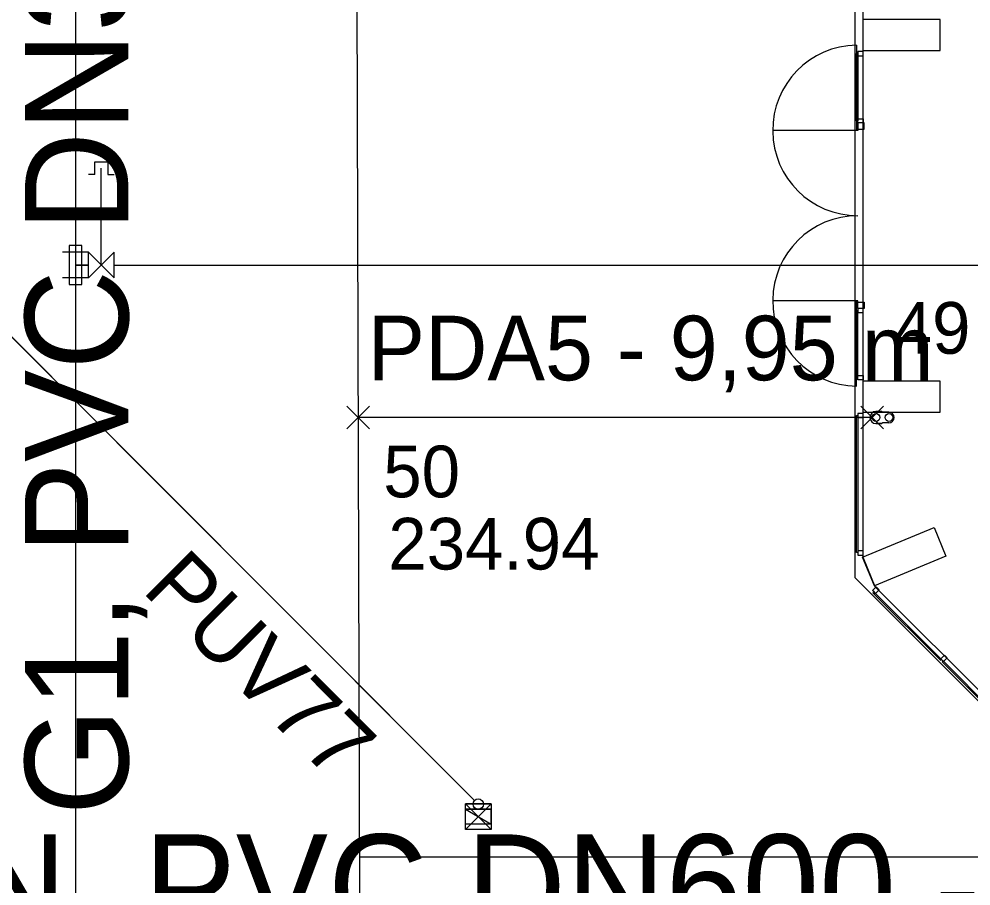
# Model space of a CAD drawing. Extents: x -264234 to -263604, y -1242346 to -1242049.
# Drawn here: x -263925.24 to -263906.8, y -1242233.35 to -1242216.57 of the extents above; entities that cross this region are included whole.
import ezdxf

# ---------------------------------------------------------------- set-up
doc = ezdxf.new("R2010")
doc.units = 0
for name, color, linetype in [('KFA_BODY_CISLO', 7, 'Continuous'), ('KFA_BODY_SYMBOL', 7, 'Continuous'), ('KFA_BODY_VYSKA', 7, 'Continuous'), ('KFA_DAZDOVA_KANALIZACIA_pripojky_tA_tC', 7, 'Continuous'), ('KFA_DAZDOVA_KANALIZACIA_pripojky_tA_tC_popis', 7, 'Continuous'), ('KFA_DAZDOVA_KANALIZACIA_retencna_nadrz_popis', 7, 'Continuous'), ('KFA_DAZDOVA_KANALIZACIA_vetva_G_popis', 7, 'Continuous'), ('KFA_JESTV_IS_DSP_-_KANAL_DAZD', 7, 'Continuous'), ('KFA_SITUACIA_DSP', 7, 'Continuous'), ('KFA_SO_40-2-II_DK_PRIPOJKY_UV_PROJEKT', 7, 'Continuous'), ('KFA_SO_40-2-II_DK_PRIPOJKY_UV_PROJEKT_popis', 7, 'Continuous'), ('KFA_SO_40-2-II_DK_UV_PROJEKT', 7, 'Continuous')]:
    doc.layers.add(name, color=color, linetype=linetype)

msp = doc.modelspace()

# ---------------------------------------------------------------- linework, layer by layer
at = {"layer": 'KFA_BODY_SYMBOL'}
for p, q in [((-263918.891, -1242224.504), (-263918.449, -1242224.062)), ((-263918.449, -1242224.504), (-263918.891, -1242224.062)), ((-263908.939, -1242224.503), (-263908.497, -1242224.061)), ((-263908.497, -1242224.503), (-263908.939, -1242224.061))]:
    msp.add_line(p, q, dxfattribs=at)
at = {"layer": 'KFA_DAZDOVA_KANALIZACIA_pripojky_tA_tC'}
msp.add_line((-263908.718, -1242224.282), (-263918.67, -1242224.283), dxfattribs=at)
at = {"layer": 'KFA_JESTV_IS_DSP_-_KANAL_DAZD'}
msp.add_line((-263918.755, -1242197.225), (-263918.632, -1242236.449), dxfattribs=at)
at = {"layer": 'KFA_SITUACIA_DSP'}
for p, q in [((-263924.143, -1242185.14), (-263924.143, -1242250.14)), ((-263908.893, -1242226.995), (-263908.893, -1242203.332)), ((-263907.398, -1242216.582), (-263908.898, -1242216.582)), ((-263908.898, -1242216.582), (-263908.898, -1242217.182)), ((-263907.398, -1242217.182), (-263907.398, -1242216.582)), ((-263909.018, -1242217.077), (-263909.018, -1242218.727)), ((-263909.018, -1242218.542), (-263909.018, -1242217.242)), ((-263909.018, -1242217.242), (-263908.993, -1242217.242)), ((-263908.893, -1242217.202), (-263908.993, -1242217.202)), ((-263908.993, -1242217.202), (-263908.993, -1242217.242)), ((-263908.993, -1242217.242), (-263908.993, -1242218.542)), ((-263908.993, -1242217.242), (-263908.993, -1242217.282)), ((-263908.898, -1242217.182), (-263907.398, -1242217.182)), ((-263908.893, -1242217.282), (-263908.893, -1242217.202)), ((-263908.993, -1242217.282), (-263908.893, -1242217.282)), ((-263908.993, -1242218.542), (-263909.018, -1242218.542)), ((-263908.993, -1242218.542), (-263908.993, -1242218.502)), ((-263908.993, -1242218.502), (-263908.893, -1242218.502)), ((-263908.993, -1242218.582), (-263908.993, -1242218.542)), ((-263908.893, -1242218.502), (-263908.893, -1242218.582)), ((-263908.993, -1242218.727), (-263910.643, -1242218.727)), ((-263908.893, -1242218.582), (-263908.993, -1242218.582)), ((-263908.873, -1242218.582), (-263908.993, -1242218.582)), ((-263908.993, -1242218.582), (-263908.993, -1242218.702)), ((-263908.993, -1242218.702), (-263908.993, -1242218.727)), ((-263908.993, -1242218.702), (-263908.873, -1242218.702)), ((-263908.873, -1242218.702), (-263908.873, -1242218.582)), ((-263923.768, -1242219.582), (-263923.768, -1242219.332)), ((-263923.768, -1242219.332), (-263923.518, -1242219.332)), ((-263923.643, -1242221.332), (-263923.643, -1242219.457)), ((-263923.518, -1242219.332), (-263923.518, -1242219.582)), ((-263923.768, -1242219.582), (-263923.893, -1242219.582)), ((-263923.518, -1242219.582), (-263923.393, -1242219.582)), ((-263923.893, -1242221.082), (-263924.393, -1242221.082)), ((-263924.018, -1242220.957), (-263924.268, -1242220.957)), ((-263924.268, -1242220.957), (-263924.268, -1242221.707)), ((-263924.018, -1242221.707), (-263924.018, -1242220.957)), ((-263923.893, -1242221.582), (-263923.893, -1242221.082)), ((-263923.893, -1242221.082), (-263923.393, -1242221.582)), ((-263923.393, -1242221.082), (-263923.893, -1242221.582)), ((-263923.393, -1242221.582), (-263923.393, -1242221.082)), ((-263924.143, -1242221.332), (-263923.893, -1242221.332)), ((-263923.893, -1242221.332), (-263924.143, -1242221.332)), ((-263923.393, -1242221.332), (-263903.343, -1242221.332)), ((-263923.893, -1242221.582), (-263924.393, -1242221.582)), ((-263924.268, -1242221.707), (-263924.018, -1242221.707)), ((-263916.414, -1242231.691), (-263926.24, -1242221.865)), ((-263908.993, -1242222.027), (-263910.643, -1242222.027)), ((-263909.018, -1242223.677), (-263909.018, -1242222.027)), ((-263908.993, -1242222.052), (-263908.993, -1242222.027)), ((-263909.018, -1242222.212), (-263909.018, -1242223.512)), ((-263908.993, -1242222.212), (-263909.018, -1242222.212)), ((-263908.993, -1242222.052), (-263908.873, -1242222.052)), ((-263908.993, -1242222.172), (-263908.993, -1242222.052)), ((-263908.893, -1242222.172), (-263908.993, -1242222.172)), ((-263908.993, -1242222.172), (-263908.993, -1242222.212)), ((-263908.873, -1242222.172), (-263908.993, -1242222.172)), ((-263908.993, -1242223.512), (-263908.993, -1242222.212)), ((-263908.993, -1242222.212), (-263908.993, -1242222.252)), ((-263908.893, -1242222.252), (-263908.893, -1242222.172)), ((-263908.873, -1242222.052), (-263908.873, -1242222.172)), ((-263908.993, -1242222.252), (-263908.893, -1242222.252)), ((-263909.018, -1242223.512), (-263908.993, -1242223.512)), ((-263908.993, -1242223.512), (-263908.993, -1242223.472)), ((-263908.993, -1242223.472), (-263908.893, -1242223.472)), ((-263908.993, -1242223.552), (-263908.993, -1242223.512)), ((-263908.893, -1242223.472), (-263908.893, -1242223.552)), ((-263908.893, -1242223.552), (-263908.993, -1242223.552)), ((-263907.398, -1242223.582), (-263908.898, -1242223.582)), ((-263908.898, -1242223.582), (-263908.898, -1242224.182)), ((-263907.398, -1242224.182), (-263907.398, -1242223.582)), ((-263909.018, -1242226.892), (-263909.018, -1242224.242)), ((-263909.018, -1242224.242), (-263908.993, -1242224.242)), ((-263908.893, -1242224.202), (-263908.993, -1242224.202)), ((-263908.993, -1242224.202), (-263908.993, -1242224.242)), ((-263908.993, -1242224.242), (-263908.993, -1242226.892)), ((-263908.993, -1242224.242), (-263908.993, -1242224.282)), ((-263908.898, -1242224.182), (-263907.398, -1242224.182)), ((-263908.893, -1242224.282), (-263908.893, -1242224.202)), ((-263908.532, -1242224.165), (-263908.643, -1242224.165)), ((-263908.518, -1242224.179), (-263908.532, -1242224.165)), ((-263908.393, -1242224.179), (-263908.518, -1242224.179)), ((-263908.718, -1242224.282), (-263918.67, -1242224.282)), ((-263908.993, -1242224.282), (-263908.893, -1242224.282)), ((-263908.643, -1242224.399), (-263908.532, -1242224.399)), ((-263908.532, -1242224.399), (-263908.643, -1242224.399)), ((-263908.518, -1242224.385), (-263908.532, -1242224.399)), ((-263908.393, -1242224.385), (-263908.518, -1242224.385)), ((-263908.903, -1242226.985), (-263907.518, -1242226.411)), ((-263907.518, -1242226.411), (-263907.288, -1242226.966)), ((-263908.993, -1242226.892), (-263909.018, -1242226.892)), ((-263908.893, -1242226.865), (-263908.993, -1242226.865)), ((-263908.993, -1242226.865), (-263908.993, -1242226.905)), ((-263908.993, -1242226.905), (-263908.993, -1242226.945)), ((-263908.993, -1242226.945), (-263908.893, -1242226.945)), ((-263908.674, -1242227.54), (-263908.903, -1242226.985)), ((-263908.893, -1242226.945), (-263908.893, -1242226.865)), ((-263908.893, -1242226.995), (-263908.663, -1242227.55)), ((-263907.288, -1242226.966), (-263908.674, -1242227.54)), ((-263908.709, -1242227.631), (-263908.638, -1242227.56)), ((-263908.663, -1242227.55), (-263895.135, -1242241.078)), ((-263908.638, -1242227.56), (-263908.581, -1242227.617)), ((-263908.68, -1242227.659), (-263908.709, -1242227.631)), ((-263908.685, -1242227.654), (-263908.703, -1242227.672)), ((-263908.703, -1242227.672), (-263907.395, -1242228.98)), ((-263907.377, -1242228.963), (-263908.685, -1242227.654)), ((-263908.652, -1242227.688), (-263908.68, -1242227.659)), ((-263908.581, -1242227.617), (-263908.652, -1242227.688)), ((-263907.395, -1242228.98), (-263907.377, -1242228.963)), ((-263907.39, -1242228.95), (-263907.319, -1242228.879)), ((-263907.361, -1242228.978), (-263907.39, -1242228.95)), ((-263907.363, -1242229.012), (-263907.345, -1242228.994)), ((-263906.055, -1242230.32), (-263907.363, -1242229.012)), ((-263907.333, -1242229.007), (-263907.361, -1242228.978)), ((-263907.345, -1242228.994), (-263906.037, -1242230.303)), ((-263907.262, -1242228.936), (-263907.333, -1242229.007)), ((-263907.319, -1242228.879), (-263907.262, -1242228.936)), ((-263916.593, -1242231.862), (-263916.093, -1242231.862)), ((-263916.593, -1242232.152), (-263916.593, -1242231.862)), ((-263916.593, -1242231.862), (-263916.093, -1242232.152)), ((-263916.593, -1242231.862), (-263916.093, -1242232.152)), ((-263916.093, -1242231.862), (-263916.593, -1242231.862)), ((-263916.093, -1242231.862), (-263916.093, -1242232.152)), ((-263916.093, -1242232.152), (-263916.093, -1242231.862)), ((-263916.093, -1242232.152), (-263916.593, -1242232.152)), ((-263905.894, -1242232.793), (-263918.643, -1242232.793))]:
    msp.add_line(p, q, dxfattribs=at)
msp.add_lwpolyline([(-263794.893, -1242227.382), (-263808.968, -1242241.457), (-263894.968, -1242241.457), (-263909.043, -1242227.382), (-263909.043, -1242196.333), (-263914.143, -1242196.333), (-263914.143, -1242132.433), (-263909.043, -1242132.433), (-263909.043, -1242101.382), (-263894.968, -1242087.307), (-263808.968, -1242087.307), (-263794.893, -1242101.382), (-263794.893, -1242227.382)], dxfattribs=at)
for centre, radius in [((-263908.643, -1242224.282), 0.075), ((-263908.393, -1242224.282), 0.075), ((-263916.343, -1242231.762), 0.1)]:
    msp.add_circle(centre, radius, dxfattribs=at)
for centre, radius, start, end in [((-263908.993, -1242218.727), 1.65, 90.8682, 270), ((-263908.993, -1242222.027), 1.65, 90, 269.1318), ((-263908.643, -1242224.282), 0.117, 90, 270), ((-263908.393, -1242224.282), 0.103, 270, 90)]:
    msp.add_arc(centre, radius, start, end, dxfattribs=at)
at = {"layer": 'KFA_SO_40-2-II_DK_PRIPOJKY_UV_PROJEKT'}
msp.add_lwpolyline([(-263916.414, -1242231.691), (-263926.24, -1242221.865)], dxfattribs=at)
at = {"layer": 'KFA_SO_40-2-II_DK_UV_PROJEKT'}
msp.add_lwpolyline([(-263916.593, -1242232.257), (-263916.593, -1242231.757), (-263916.093, -1242231.757), (-263916.093, -1242232.257), (-263916.593, -1242232.257), (-263916.093, -1242231.757), (-263916.593, -1242231.757), (-263916.093, -1242232.257)], dxfattribs=at)

# ---------------------------------------------------------------- texts
at = {"layer": 'KFA_BODY_CISLO'}
for s, p in [('49', (-263908.301, -1242223.049)), ('50', (-263918.184, -1242225.827))]:
    msp.add_text(s, height=1, dxfattribs=at).set_placement(p)
at = {"layer": 'KFA_BODY_VYSKA'}
msp.add_text('234.94', height=1, dxfattribs=at).set_placement((-263918.086, -1242227.224))
at = {"layer": 'KFA_DAZDOVA_KANALIZACIA_pripojky_tA_tC_popis'}
msp.add_text('PDA5 - 9,95 m', height=1.25, dxfattribs=at).set_placement((-263918.489, -1242223.563))
at = {"layer": 'KFA_DAZDOVA_KANALIZACIA_retencna_nadrz_popis'}
msp.add_text('NRN, PVC DN600 - 8,17 m', height=2, dxfattribs=at).set_placement((-263930.102, -1242234.349))
at = {"layer": 'KFA_DAZDOVA_KANALIZACIA_vetva_G_popis'}
msp.add_text('G1, PVC DN300 - 16,96 m', height=2, rotation=90, dxfattribs=at).set_placement((-263923.121, -1242231.981))
at = {"layer": 'KFA_SO_40-2-II_DK_PRIPOJKY_UV_PROJEKT_popis'}
msp.add_text('PUV77', height=1.25, rotation=315.0029, dxfattribs=at).set_placement((-263922.875, -1242227.639))

doc.saveas('drawing.dxf')
